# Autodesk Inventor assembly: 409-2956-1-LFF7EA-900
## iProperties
Created: 2010-09
Part Number: 409-2956-1-LFF7EA-900
Document SubType Name: Assembly
Designer: S. Boerckel
Mass: 2.71449e+06 g
Surface Area: 794951 cm^2
Volume: 404621 cm^3
Density: 6.70872 g/cm^3
Description: GENERAL ARRANGEMENT UNIT 298034
Material: ASSEMBLY
SMR: =<MATERIAL>
Author: S. Boerckel
Revision Number: 0
Title: GENERAL ARRANGEMENT UNIT-298034
